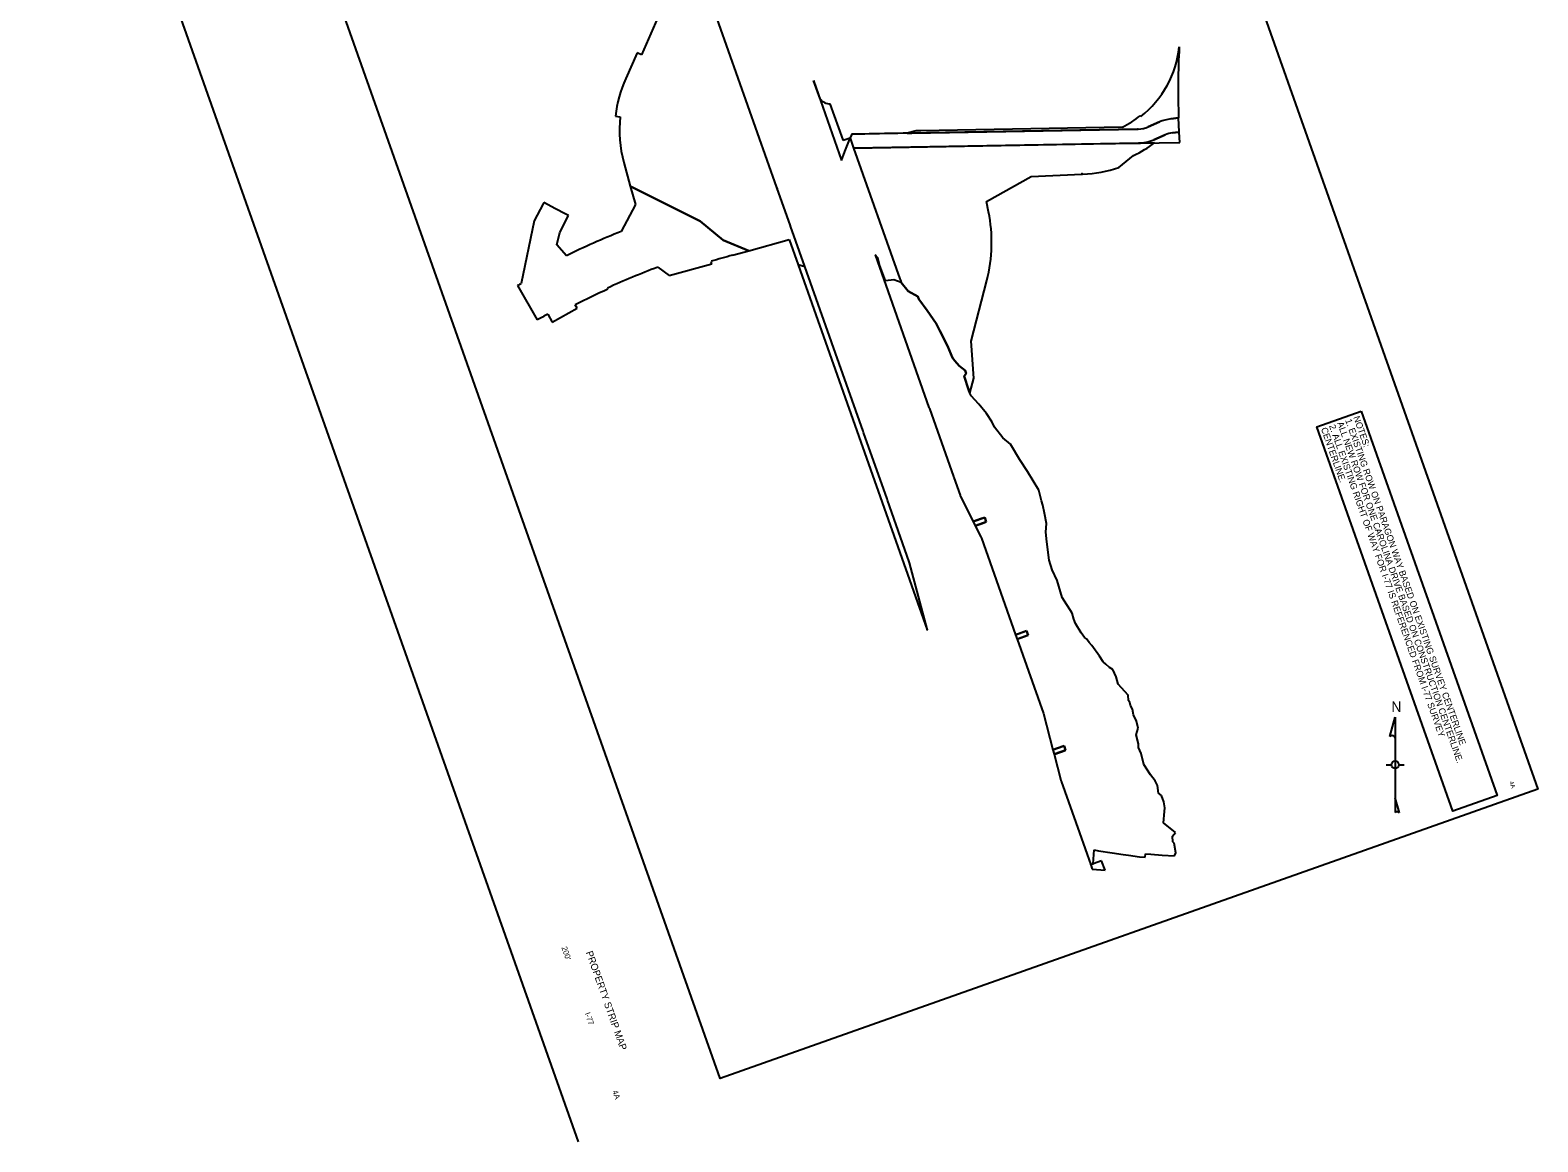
# Model space of a CAD drawing. Extents: x 2002566 to 2009026, y 1133033 to 1140744.
# Drawn here: x 2002566 to 2009026, y 1133033 to 1137795 of the extents above; entities that cross this region are included whole.
import ezdxf

# ---------------------------------------------------------------- set-up
doc = ezdxf.new("R2010")
doc.units = 0
for name, color, linetype in [('RD_DDB_Profile_EX', 7, 'Continuous'), ('RD_EX_DV_Prop', 7, 'Continuous'), ('RD_EX_Easement', 7, 'Continuous'), ('RD_PD_DR_ErosCtrl', 7, 'Continuous'), ('RD_PD_RW', 7, 'Continuous')]:
    doc.layers.add(name, color=color, linetype=linetype)

msp = doc.modelspace()

# ---------------------------------------------------------------- linework, layer by layer
at = {"layer": 'RD_DDB_Profile_EX'}
msp.add_lwpolyline([(2006833, 1140744.3), (2009026.3, 1134544.6), (2005522.1, 1133305), (2003328.9, 1139504.6)], close=True, dxfattribs=at)
at = {"layer": 'RD_EX_DV_Prop'}
for p, q in [((2005765.9, 1137120.8), (2005340.4, 1138323.7)), ((2005275.3, 1137895), (2005185, 1137690.4)), ((2005166.7, 1137698.5), (2005117.8, 1137588.3)), ((2005185, 1137690.4), (2005166.7, 1137698.5)), ((2005951.3, 1137501.2), (2005921.8, 1137579.9)), ((2005921.8, 1137579.9), (2006042.8, 1137237.7)), ((2006048.9, 1137325.4), (2005994.3, 1137479.8)), ((2005074.2, 1137426.8), (2005094.1, 1137424.6)), ((2007325.4, 1137425.1), (2007322.3, 1137429)), ((2007356.7, 1137381.2), (2007404.9, 1137402)), ((2007404.9, 1137402), (2007356.7, 1137381.2)), ((2007404.9, 1137402), (2007404.9, 1137402)), ((2007404.9, 1137402), (2007404.9, 1137402)), ((2007453, 1137415.3), (2007487.1, 1137419.7)), ((2007487.1, 1137419.7), (2007453, 1137415.3)), ((2007453, 1137415.3), (2007453, 1137415.3)), ((2007453, 1137415.3), (2007453, 1137415.3)), ((2007489.7, 1137359.2), (2007487.1, 1137419.7)), ((2006079.2, 1137332.9), (2006049.9, 1137322.5)), ((2006057.1, 1137275.2), (2006079.2, 1137332.9)), ((2006079.5, 1137333.9), (2006079.2, 1137332.9)), ((2006079.2, 1137332.9), (2006079.5, 1137333.9)), ((2006079.5, 1137333.9), (2006079.2, 1137332.9)), ((2006079.2, 1137332.9), (2006094.4, 1137289.7)), ((2006084.5, 1137346.9), (2006079.5, 1137333.9)), ((2006079.5, 1137333.9), (2006079.5, 1137333.9)), ((2006085.5, 1137349.5), (2006084.5, 1137346.9)), ((2006362.5, 1137364.5), (2006323.6, 1137353.8)), ((2006323.6, 1137353.8), (2006343.8, 1137354.1)), ((2006343.8, 1137354.1), (2007308.7, 1137371.3)), ((2006382.6, 1137364.8), (2006362.5, 1137364.5)), ((2007246.6, 1137380.2), (2006382.6, 1137364.8)), ((2007308.7, 1137371.3), (2007311.2, 1137371.4)), ((2007356.6, 1137381.2), (2007356.7, 1137381.2)), ((2007356.7, 1137381.2), (2007356.6, 1137381.2)), ((2007380.5, 1137326.1), (2007428.7, 1137346.9)), ((2007485.8, 1137359), (2007460.7, 1137355.8)), ((2007460.7, 1137355.8), (2007485.8, 1137359)), ((2007492.4, 1137314.6), (2007489.7, 1137359.1)), ((2006042.8, 1137237.7), (2006057.1, 1137275.2)), ((2006049.9, 1137322.5), (2006048.9, 1137325.4)), ((2006094.4, 1137289.7), (2006095.1, 1137289.7)), ((2006095.1, 1137289.7), (2006094.4, 1137289.7)), ((2006094.4, 1137289.7), (2006292.1, 1136730.8)), ((2006095.1, 1137289.7), (2007122.1, 1137308)), ((2007122.1, 1137308), (2007312.3, 1137311.4)), ((2007312.3, 1137311.4), (2007315.4, 1137311.4)), ((2007312.3, 1137311.4), (2007315.4, 1137311.4)), ((2007315.4, 1137311.4), (2007492.4, 1137314.6)), ((2007380.5, 1137326.1), (2007380.5, 1137326.1)), ((2005109.7, 1137227.9), (2005137.3, 1137127.8)), ((2007231.1, 1137206.6), (2007293.8, 1137258.5)), ((2006664, 1137060.8), (2006854.7, 1137168.6)), ((2006854.7, 1137168.6), (2007072.7, 1137178)), ((2005436.8, 1136977.2), (2005137.3, 1137127.8)), ((2005137.3, 1137127.8), (2005159.2, 1137048.2)), ((2005137.3, 1137127.8), (2005436.8, 1136977.2)), ((2004763.7, 1137051.1), (2004725.6, 1136978.8)), ((2004766.8, 1137057), (2004763.7, 1137051.1)), ((2004816.9, 1137030.6), (2004766.8, 1137057)), ((2004858.1, 1137008.8), (2004816.9, 1137030.6)), ((2004873, 1137001), (2004858.1, 1137008.8)), ((2005159.2, 1137048.2), (2005098.1, 1136933.4)), ((2006672.7, 1137017.4), (2006664, 1137060.8)), ((2004725.6, 1136978.8), (2004669.3, 1136709.9)), ((2004834.8, 1136928.6), (2004873, 1137001)), ((2005534.7, 1136896.2), (2005436.8, 1136977.2)), ((2005436.8, 1136977.2), (2005534.7, 1136896.2)), ((2005534.7, 1136896.2), (2005436.8, 1136977.2)), ((2005436.8, 1136977.2), (2005534.7, 1136896.2)), ((2005885.7, 1136782.3), (2005824.2, 1136956.1)), ((2004822, 1136875.4), (2004834.8, 1136928.6)), ((2005644.8, 1136850.6), (2005534.7, 1136896.2)), ((2005534.7, 1136896.2), (2005644.8, 1136850.6)), ((2005644.8, 1136850.6), (2005818.1, 1136898.3)), ((2005818.1, 1136898.3), (2005856.6, 1136789.5)), ((2004863.5, 1136828.9), (2004822, 1136875.4)), ((2005574.7, 1136831.3), (2005644.8, 1136850.6)), ((2006185.9, 1136833.4), (2006417.2, 1136179.4)), ((2005254.6, 1136779.8), (2005304, 1136744.5)), ((2005304, 1136744.5), (2005487.2, 1136794.9)), ((2005487.2, 1136794.9), (2005484.4, 1136805.1)), ((2005885.7, 1136782.3), (2005856.6, 1136789.5)), ((2005856.6, 1136789.5), (2006409.4, 1135227)), ((2005856.6, 1136789.5), (2005885.7, 1136782.3)), ((2005999.4, 1136460.8), (2005885.7, 1136782.3)), ((2004654.6, 1136701.5), (2004738.9, 1136553.9)), ((2005041.1, 1136685.9), (2005039.1, 1136690.5)), ((2006266.7, 1136726.5), (2006266.7, 1136726.5)), ((2006298, 1136714.2), (2006266.7, 1136726.5)), ((2006292.1, 1136730.8), (2006294.5, 1136724)), ((2006294.5, 1136724), (2006298, 1136714.2)), ((2006298, 1136714.2), (2006327.8, 1136677.6)), ((2006598.3, 1136462.6), (2006665, 1136722.9)), ((2004909.4, 1136603.8), (2004901.1, 1136618.6)), ((2004783.5, 1136579), (2004802.9, 1136544.2)), ((2004802.9, 1136544.2), (2004909.4, 1136603.8)), ((2005999.4, 1136460.8), (2005999.4, 1136460.8)), ((2006135, 1136077.5), (2006001.3, 1136455.6)), ((2006609.5, 1136304.9), (2006598.3, 1136462.6)), ((2006517.8, 1136392), (2006527.7, 1136379)), ((2006592.9, 1136240.1), (2006609.5, 1136304.9)), ((2006586.3, 1136256), (2006592.9, 1136240.1)), ((2006417.2, 1136179.4), (2006418, 1136177.1)), ((2006418, 1136177.1), (2006418.2, 1136176.6)), ((2006418.2, 1136176.6), (2006419, 1136174.4)), ((2006419, 1136174.4), (2006521.7, 1135883.9)), ((2006135, 1136077.5), (2006135, 1136077.5)), ((2006237.6, 1135787.4), (2006136.8, 1136072.4)), ((2006521.7, 1135883.9), (2006522.5, 1135881.8)), ((2006522.5, 1135881.8), (2006522.7, 1135881.2)), ((2006522.7, 1135881.2), (2006523.5, 1135878.9)), ((2006523.5, 1135878.9), (2006550.3, 1135803.2)), ((2006887.6, 1135825.2), (2006838.8, 1135904.2)), ((2006237.6, 1135787.4), (2006237.6, 1135787.4)), ((2006332.9, 1135518.2), (2006239.5, 1135782.2)), ((2006550.3, 1135803.2), (2006550.9, 1135801.4)), ((2006550.9, 1135801.4), (2006551.2, 1135800.5)), ((2006551.2, 1135800.5), (2006551.3, 1135800.4)), ((2006551.3, 1135800.4), (2006552.4, 1135798.2)), ((2006552.4, 1135798.2), (2006606.4, 1135690.8)), ((2006912.6, 1135726.9), (2006905.3, 1135760.7)), ((2006920.5, 1135681.4), (2006912.6, 1135726.9)), ((2006606.4, 1135690.8), (2006655.9, 1135708.2)), ((2006638.4, 1135702), (2006606.4, 1135690.8)), ((2006606.4, 1135690.8), (2006615.5, 1135672.7)), ((2006662.6, 1135689.2), (2006615.5, 1135672.7)), ((2006615.5, 1135672.7), (2006644.4, 1135682.8)), ((2006615.5, 1135672.7), (2006639.5, 1135624.9)), ((2006655.9, 1135708.2), (2006638.4, 1135702)), ((2006644.4, 1135682.8), (2006662.6, 1135689.2)), ((2006662.6, 1135689.2), (2006655.9, 1135708.2)), ((2006655.9, 1135708.2), (2006662.6, 1135689.2)), ((2006918.2, 1135644.8), (2006920.5, 1135681.4)), ((2006639.5, 1135624.9), (2006640.4, 1135623.2)), ((2006640.4, 1135623.2), (2006640.8, 1135622.3)), ((2006640.8, 1135622.3), (2006640.9, 1135622.1)), ((2006640.9, 1135622.1), (2006641.7, 1135619.9)), ((2006641.7, 1135619.9), (2006788.3, 1135205.5)), ((2006921.7, 1135603.2), (2006918.2, 1135644.8)), ((2006931.5, 1135524.9), (2006921.7, 1135603.2)), ((2006945.5, 1135484.1), (2006931.5, 1135524.9)), ((2006410.3, 1135224.5), (2006334.4, 1135513.2)), ((2006966.9, 1135437.5), (2006945.5, 1135484.1)), ((2006988.6, 1135364.6), (2006966.9, 1135437.5)), ((2007030.5, 1135298), (2006988.6, 1135364.6)), ((2007038.1, 1135271.8), (2007030.5, 1135298)), ((2007045.1, 1135253.7), (2007038.1, 1135271.8)), ((2006409.4, 1135227), (2006410.3, 1135224.5)), ((2006788.3, 1135205.5), (2006835.5, 1135222.1)), ((2006789.6, 1135206), (2006788.3, 1135205.5)), ((2006788.3, 1135205.5), (2006794.9, 1135186.8)), ((2006801.1, 1135210), (2006789.6, 1135206)), ((2006842.1, 1135203.4), (2006794.9, 1135186.8)), ((2006835.5, 1135222.1), (2006801.1, 1135210)), ((2006807, 1135191), (2006842.1, 1135203.4)), ((2006842.1, 1135203.4), (2006835.5, 1135222.1)), ((2006835.5, 1135222.1), (2006842.1, 1135203.4)), ((2006794.9, 1135186.8), (2006907.7, 1134867.8)), ((2007148.5, 1135114), (2007115.2, 1135159.8)), ((2007163.9, 1135090.2), (2007148.5, 1135114)), ((2007175.3, 1135080.1), (2007163.9, 1135090.2)), ((2007218.7, 1135025.7), (2007205.2, 1135056.6)), ((2007228.3, 1134993.2), (2007218.7, 1135025.7)), ((2006907.7, 1134867.8), (2006948.2, 1134712.8)), ((2006948.2, 1134712.8), (2006996, 1134729.6)), ((2006963.7, 1134718.2), (2006948.2, 1134712.8)), ((2006948.2, 1134712.8), (2006953.3, 1134693.5)), ((2007002.5, 1134710.8), (2006953.3, 1134693.5)), ((2006953.3, 1134693.5), (2006956.2, 1134694.5)), ((2006953.3, 1134693.5), (2006982.1, 1134583.2)), ((2006956.2, 1134694.5), (2007000.3, 1134710)), ((2006996, 1134729.6), (2006963.7, 1134718.2)), ((2007001.7, 1134713.1), (2006996, 1134729.6)), ((2006996, 1134729.6), (2007002.5, 1134710.8)), ((2007000.3, 1134710), (2007002.5, 1134710.8)), ((2007002.5, 1134710.8), (2007001.7, 1134713.1)), ((2007326.5, 1134697.1), (2007314.4, 1134722.7)), ((2006982.1, 1134583.2), (2006982.7, 1134581.1)), ((2006982.7, 1134581.1), (2006982.8, 1134580.6)), ((2006982.8, 1134580.6), (2006982.9, 1134580.4)), ((2006982.9, 1134580.4), (2006983.7, 1134578.2)), ((2006983.7, 1134578.2), (2007061.8, 1134357.2)), ((2007423.1, 1134489.3), (2007414.2, 1134517.2)), ((2007061.8, 1134357.2), (2007110.2, 1134220.5)), ((2007121.2, 1134224.4), (2007125.3, 1134283.6)), ((2007157.1, 1134237.2), (2007121.2, 1134224.4)), ((2007125.3, 1134283.6), (2007144.1, 1134280.5)), ((2007144.1, 1134280.5), (2007202.3, 1134270.9)), ((2007171.7, 1134196.4), (2007157.1, 1134237.2)), ((2007202.3, 1134270.9), (2007249.8, 1134263.8)), ((2007249.8, 1134263.8), (2007271.9, 1134260.7)), ((2007271.9, 1134260.7), (2007319.5, 1134254.6)), ((2007319.5, 1134254.6), (2007343.3, 1134252.1)), ((2007343.3, 1134252.1), (2007344.7, 1134267.1)), ((2007344.7, 1134267.1), (2007368.5, 1134265)), ((2007368.5, 1134265), (2007416.1, 1134261.3)), ((2007416.1, 1134261.3), (2007469.8, 1134258.6)), ((2007121.2, 1134224.4), (2007110.2, 1134220.5)), ((2007110.2, 1134220.5), (2007110.4, 1134220.6)), ((2007110.2, 1134220.5), (2007116.8, 1134201.9)), ((2007110.4, 1134220.6), (2007110.7, 1134220.7)), ((2007110.7, 1134220.7), (2007121.2, 1134224.4)), ((2007116.8, 1134201.9), (2007171.7, 1134196.4))]:
    msp.add_line(p, q, dxfattribs=at)
for points in [[(2007311.2, 1137371.4), (2007311.2, 1137371.4), (2006323.6, 1137353.8)], [(2007428.7, 1137346.9), (2007380.5, 1137326.1)], [(2007384.2, 1137312.7), (2007315.4, 1137311.4), (2006095.1, 1137289.7)], [(2007074.2, 1137178.1), (2007072.6, 1137181), (2007077.1, 1137178.2)], [(2005766.1, 1137120.5), (2005765.7, 1137121.6)], [(2005824.2, 1136956.1), (2005824, 1136956.6), (2005765.9, 1137120.8)], [(2005767.5, 1137116.4), (2005766.1, 1137120.5)], [(2005825.8, 1136951.6), (2005824.1, 1136956.4)], [(2006266.7, 1136726.5), (2006230.7, 1136722.1), (2006217.9, 1136756), (2006205.2, 1136789.9), (2006198.6, 1136820.1), (2006185.9, 1136833.4)], [(2006597.7, 1136228.6), (2006592.9, 1136240.1), (2006586.3, 1136256), (2006567.6, 1136313.2), (2006576.7, 1136324.9), (2006571.8, 1136337.4), (2006546.2, 1136357.7), (2006527.7, 1136379), (2006517.8, 1136392), (2006496.2, 1136443.2), (2006463.2, 1136506.8), (2006448.7, 1136538.5), (2006409.2, 1136595.1), (2006374.4, 1136642.5), (2006369.8, 1136653.9), (2006327.8, 1136677.6), (2006298, 1136714.2)], [(2006327.8, 1136677.6), (2006369.8, 1136653.9), (2006374.4, 1136642.5), (2006409.2, 1136595.1), (2006448.7, 1136538.5)], [(2006448.7, 1136538.5), (2006463.2, 1136506.8), (2006496.2, 1136443.2), (2006517.8, 1136392)], [(2006001.3, 1136455.6), (2005999.4, 1136460.8)], [(2006527.7, 1136379), (2006546.2, 1136357.7), (2006571.8, 1136337.4)], [(2006571.8, 1136337.4), (2006576.7, 1136324.9), (2006567.6, 1136313.2), (2006586.3, 1136256)], [(2006688, 1136116.1), (2006663.6, 1136153.4), (2006630.9, 1136192.7), (2006597.7, 1136228.6)], [(2006765.9, 1136021.4), (2006733.5, 1136049.7), (2006698.1, 1136094.4), (2006688, 1136116.1)], [(2006136.8, 1136072.4), (2006135, 1136077.5)], [(2006838.8, 1135904.2), (2006807, 1135955.1), (2006765.9, 1136021.4)], [(2006239.5, 1135782.2), (2006237.6, 1135787.4)], [(2006905.3, 1135760.7), (2006899.8, 1135779.9), (2006887.6, 1135825.2)], [(2006334.4, 1135513.2), (2006332.9, 1135518.2)], [(2007083.4, 1135193.2), (2007068.7, 1135213.8), (2007045.1, 1135253.7)], [(2006794.9, 1135186.8), (2006797.8, 1135187.8), (2006807, 1135191)], [(2007115.2, 1135159.8), (2007103.7, 1135173), (2007091.9, 1135187.9), (2007083.4, 1135193.2)], [(2007205.2, 1135056.6), (2007191.4, 1135065.4), (2007175.3, 1135080.1)], [(2007271.5, 1134924.4), (2007270.1, 1134947), (2007228.3, 1134993.2)], [(2007280.2, 1134902.6), (2007278.5, 1134915.8), (2007271.5, 1134924.4)], [(2007313.4, 1134805.8), (2007305.9, 1134835.8), (2007293.1, 1134863), (2007289.3, 1134887.3), (2007280.2, 1134902.6)], [(2007314.4, 1134722.7), (2007314.8, 1134738.4), (2007305.2, 1134776.3), (2007313.4, 1134805.8)], [(2007366.5, 1134605.5), (2007337.4, 1134650.3), (2007326.5, 1134697.1)], [(2007396.8, 1134559.6), (2007386.7, 1134579.9), (2007366.5, 1134605.5)], [(2007414.2, 1134517.2), (2007400.6, 1134526.4), (2007396.8, 1134559.6)], [(2007427, 1134449.1), (2007427.7, 1134464.8), (2007423.1, 1134489.3)], [(2007473.6, 1134359.1), (2007422.6, 1134400.2), (2007427, 1134449.1)], [(2007468.3, 1134313), (2007462.7, 1134318.9), (2007461, 1134342.9), (2007473.6, 1134359.1)], [(2007469.8, 1134258.6), (2007475.5, 1134271.2), (2007468.3, 1134313)]]:
    msp.add_lwpolyline(points, dxfattribs=at)
for centre, radius, start, end in [((2007047.3, 1137772.5), 445, 308.69178, 353.69267), ((2011139.8, 1137542.4), 3654.8, 177.15949, 181.92434), ((2005613, 1137368), 542.1, 156.01974, 173.76924), ((2005992.3, 1137529.8), 50, 214.7982, 272.26333), ((2005616.4, 1137367.3), 525.5, 173.73148, 195.37834), ((2007047.3, 1137772.5), 440, 296.94338, 308.69178), ((2007476.3, 1137236.8), 180, 97.43537, 113.36678), ((2007476.3, 1137236.8), 180, 97.43537, 113.36678), ((2007309.1, 1137491.3), 120, 271.02947, 272.23744), ((2007309.1, 1137491.3), 120, 272.23744, 293.36527), ((2007309.1, 1137491.3), 120, 272.46021, 293.36527), ((2007476.3, 1137236.8), 120, 97.43537, 113.36837), ((2007476.3, 1137236.8), 120, 97.43537, 113.36837), ((2007488.5, 1137338.2), 21, 86.7872, 97.43541), ((2007488.5, 1137338.2), 21, 86.7872, 97.43541), ((2007047.3, 1137772.5), 570, 295.62863, 306.23172), ((2007309.1, 1137491.3), 180, 271.02972, 293.36871), ((2007309.1, 1137491.3), 180, 272.00341, 293.36666), ((2007047.3, 1137772.5), 595, 272.87194, 287.99349), ((2007047.3, 1137772.5), 595, 272.45467, 272.59205), ((2006024.7, 1136887), 661, 345.62808, 11.38239), ((2006499.8, 1133470.3), 3736, 112.0356, 115.97508), ((2006499.8, 1133470.3), 3486, 105.38893, 106.93458), ((2006499.8, 1133470.3), 3536, 110.61739, 114.39929), ((2006499.8, 1133470.3), 3721, 119.46726, 119.72801), ((2006499.8, 1133470.3), 3531, 114.39929, 116.92074), ((2006499.8, 1133470.3), 3551, 118.90294, 119.72801)]:
    msp.add_arc(centre, radius, start, end, dxfattribs=at)
for points in [[(2006323.6, 1137353.8), (2006323.6, 1137353.8), (2006323.6, 1137353.8), (2006085.5, 1137349.5), (2006085.5, 1137349.5), (2006085.5, 1137349.5)], [(2007314.2, 1137371.5), (2007314.2, 1137371.5), (2007314.2, 1137371.5), (2007313.7, 1137371.4), (2007311.2, 1137371.4), (2007311.2, 1137371.4), (2007311.2, 1137371.4), (2007311.2, 1137371.4)]]:
    msp.add_open_spline(points, degree=3, dxfattribs=at)
at = {"layer": 'RD_EX_Easement'}
msp.add_line((2006771.2, 1137370.5), (2006771.4, 1137370.5), dxfattribs=at)
at = {"layer": 'RD_PD_DR_ErosCtrl'}
msp.add_line((2002565.6, 1139670.3), (2004913.5, 1133033.4), dxfattribs=at)
msp.add_lwpolyline([(2008269.6, 1136162.6), (2008851.8, 1134516.8), (2008662.1, 1134449.8), (2008079.9, 1136095.5)], close=True, dxfattribs=at)
at = {"layer": 'RD_PD_RW'}
for p, q in [((2008391.3, 1134769), (2008414.9, 1134853.2)), ((2008414.9, 1134853.2), (2008414.9, 1134764.5)), ((2008414.9, 1134853.2), (2008414.9, 1134444.2)), ((2008376.1, 1134648.7), (2008398.8, 1134648.7)), ((2008431, 1134648.7), (2008453.7, 1134648.7)), ((2008414.9, 1134507.6), (2008414.9, 1134444.2)), ((2008433.1, 1134443.3), (2008414.9, 1134507.6))]:
    msp.add_line(p, q, dxfattribs=at)
msp.add_circle((2008414.9, 1134648.7), 16.1, dxfattribs=at)
for centre, radius, start, end in [((2008401.6, 1134759), 14.3, 22.37065, 136.13874), ((2008423.5, 1134434.2), 13.2, 43.33968, 130.56069)]:
    msp.add_arc(centre, radius, start, end, dxfattribs=at)

# ---------------------------------------------------------------- texts
at = {"layer": 'RD_PD_DR_ErosCtrl'}
for s, height, rotation, p in [('2. ALL EXISTING RIGHT OF WAY FOR I-77 IS REFERENCED FROM I-77 SURVEY', 28, 289.44941, (2008131.1, 1136100.3)), ('ALL NEW ROW FOR ONE CAROLINA DRIVE BASED ON CONSTRUCTION CENTERLINE.', 28, 289.44941, (2008165.7, 1136112.6)), ('1. EXISTING ROW ON PARAGON WAY BASED ON EXISTING SURVEY CENTERLINE', 28, 289.44941, (2008200.4, 1136124.8)), ('NOTES:', 28, 289.44941, (2008235, 1136137)), ('CENTERLINE.', 28, 289.44941, (2008096.4, 1136088.1)), ('4A', 18, 289.48201, (2008903.9, 1134574.8)), ("200'", 24, 289.48201, (2004841.9, 1133865.6)), ('PROPERTY STRIP MAP', 30, 289.48201, (2004946.5, 1133844.9)), ('I-77', 24, 289.48201, (2004941.7, 1133583.4)), ('4A', 24, 289.48201, (2005059.7, 1133249.9))]:
    msp.add_text(s, height=height, rotation=rotation, dxfattribs=at).set_placement(p)
at = {"layer": 'RD_PD_RW'}
msp.add_text('N', height=44.6, dxfattribs=at).set_placement((2008398.6, 1134875.1))

doc.saveas('drawing.dxf')
